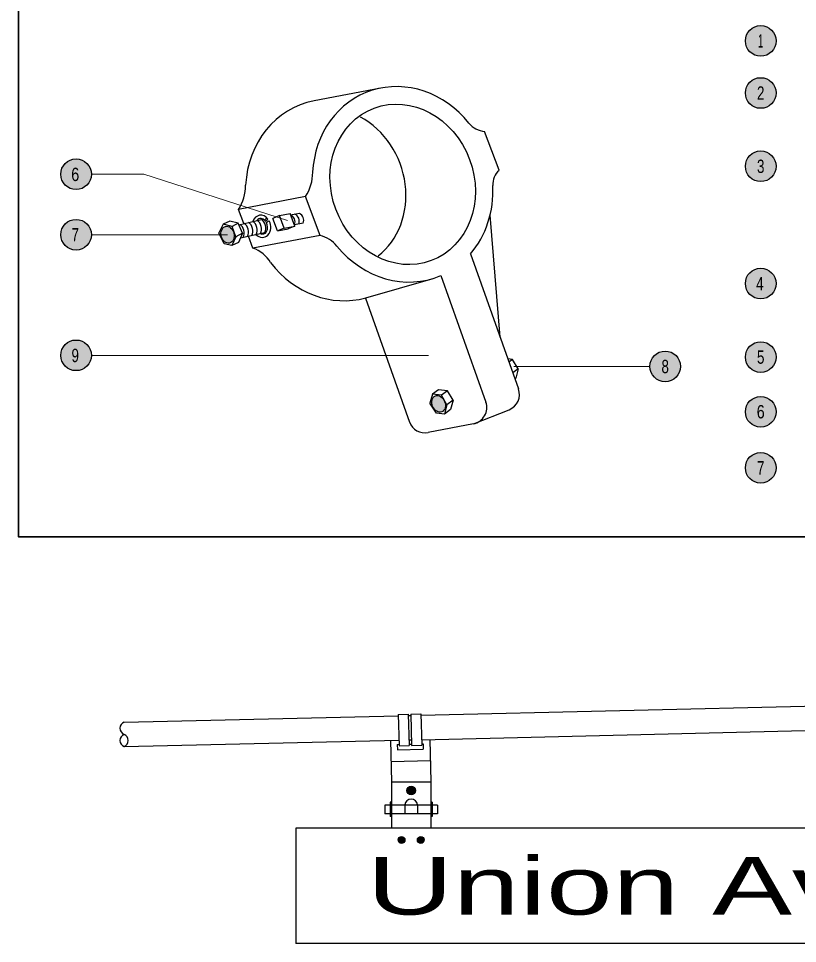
# Model space of a CAD drawing. Extents: x 312583 to 312853, y 144376 to 144586.
# Drawn here: x 312727.3 to 312771.1, y 144475.2 to 144527.1 of the extents above; entities that cross this region are included whole.
import ezdxf
from ezdxf.enums import TextEntityAlignment as Align

# ---------------------------------------------------------------- set-up
doc = ezdxf.new("R2010")
doc.units = 0
doc.header["$LTSCALE"] = 0.3
doc.layers.add('1', color=7, linetype='Continuous', lineweight=25)
doc.layers.add('2', color=7, linetype='Continuous', lineweight=13)

msp = doc.modelspace()

# ---------------------------------------------------------------- hatches: boundary and pattern name
at = {"layer": '1'}
h = msp.add_hatch(color=256, dxfattribs=at)
edge = h.paths.add_edge_path()
edge.add_ellipse((312739.0765, 144514.9847), major_axis=(0.1132, -0.4662), ratio=0.761491, start_angle=0, end_angle=360)
h = msp.add_hatch(color=256, dxfattribs=at)
edge = h.paths.add_edge_path()
edge.add_ellipse((312750.9188, 144505.4948), major_axis=(0.1834, -0.4433), ratio=0.761491, start_angle=0, end_angle=360)
for points in [[(312749.6201, 144483.7997, 1), (312749.1381, 144483.7997, 1)], [(312749.5488, 144483.7997, 1), (312749.2094, 144483.7997, 1)], [(312749.0308, 144481.0248, 1), (312748.6485, 144481.0248, 1)], [(312750.1096, 144481.0248, 1), (312749.7273, 144481.0248, 1)]]:
    msp.add_hatch(color=256, dxfattribs=at).paths.add_polyline_path(points)
at = {"layer": '2'}
for points in [[(312769.8524, 144525.8569, 1), (312768.1321, 144525.8569, 1)], [(312769.8524, 144522.9359, 1), (312768.1321, 144522.9359, 1)], [(312769.8524, 144518.8226, 1), (312768.1321, 144518.8226, 1)], [(312731.4329, 144518.3756, 1), (312729.7127, 144518.3756, 1)], [(312731.4329, 144514.9863, 1), (312729.7127, 144514.9863, 1)], [(312769.8524, 144512.2449, 1), (312768.1321, 144512.2449, 1)], [(312731.4329, 144508.217, 1), (312729.7127, 144508.217, 1)], [(312769.8524, 144508.1186, 1), (312768.1321, 144508.1186, 1)], [(312764.4923, 144507.5966, 1), (312762.772, 144507.5966, 1)], [(312769.8524, 144505.0489, 1), (312768.1321, 144505.0489, 1)], [(312769.8524, 144501.9057, 1), (312768.1321, 144501.9057, 1)]]:
    msp.add_hatch(color=256, dxfattribs=at).paths.add_polyline_path(points)

# ---------------------------------------------------------------- linework, layer by layer
at = {"layer": '1'}
for p, q in [((312747.6675, 144523.2086), (312743.9263, 144522.4955)), ((312754.3164, 144518.5969), (312753.5015, 144520.7731)), ((312743.454, 144517.1245), (312739.6851, 144516.4022)), ((312744.2689, 144514.9484), (312743.454, 144517.1245)), ((312739.9907, 144515.6058), (312739.6851, 144516.4022)), ((312739.7036, 144515.541), (312740.9723, 144515.8374)), ((312741.1482, 144515.8003), (312741.2779, 144515.9392)), ((312741.2038, 144515.754), (312741.3427, 144515.8651)), ((312741.2501, 144515.6707), (312741.4168, 144515.7633)), ((312741.9816, 144516.0596), (312741.6112, 144515.9022)), ((312741.8798, 144515.1984), (312741.6112, 144515.9022)), ((312741.9816, 144516.0596), (312742.5836, 144516.18)), ((312742.2502, 144515.3558), (312741.9816, 144516.0596)), ((312742.8521, 144515.4669), (312742.5836, 144516.18)), ((312742.6113, 144516.0966), (312743.1021, 144516.1892)), ((312754.3719, 144509.2348), (312753.8071, 144516.0874)), ((312738.8239, 144515.5781), (312738.5924, 144515.0965)), ((312739.6666, 144515.6244), (312739.3239, 144515.4392)), ((312739.9073, 144515.0688), (312739.6666, 144515.6244)), ((312742.2502, 144515.3558), (312741.8798, 144515.1984)), ((312741.8798, 144515.1984), (312742.4817, 144515.3095)), ((312742.2502, 144515.3558), (312742.8521, 144515.4669)), ((312742.8521, 144515.4669), (312742.4817, 144515.3095)), ((312742.8243, 144515.5503), (312743.3151, 144515.6429)), ((312739.9073, 144515.0688), (312739.6943, 144514.5502)), ((312739.7962, 144514.8095), (312741.1575, 144515.1058)), ((312740.5, 144514.2261), (312740.2407, 144514.9021)), ((312744.2689, 144514.9484), (312740.5, 144514.2261)), ((312739.6943, 144514.5502), (312739.3147, 144514.3742)), ((312752.7051, 144513.9112), (312755.3998, 144506.3363)), ((312751.0382, 144512.6888), (312753.5663, 144505.5954)), ((312746.8248, 144511.4387), (312750.6123, 144512.5314)), ((312746.8063, 144511.4294), (312749.2788, 144504.4749)), ((312755.0665, 144507.9846), (312754.7979, 144508.0124)), ((312755.0665, 144507.9846), (312754.8627, 144507.8272)), ((312755.3906, 144507.466), (312755.0665, 144507.9846)), ((312755.3906, 144507.466), (312755.0757, 144507.2345)), ((312755.3906, 144507.466), (312755.2517, 144506.9289)), ((312755.2517, 144506.9289), (312755.2054, 144506.8919)), ((312750.566, 144506.0307), (312750.4178, 144505.5306)), ((312751.4086, 144506.2251), (312751.0845, 144505.9751)), ((312751.7328, 144505.7066), (312751.4086, 144506.2251)), ((312751.7328, 144505.7066), (312751.5939, 144505.1695)), ((312752.8718, 144504.3731), (312754.872, 144505.1602)), ((312752.8718, 144504.3731), (312750.3252, 144503.8823)), ((312749.9268, 144488.0237), (312774.5963, 144488.6071)), ((312733.2675, 144487.6348), (312748.6489, 144487.9959)), ((312748.6489, 144488.07), (312749.2138, 144488.0885)), ((312748.6489, 144488.07), (312748.6952, 144486.3105)), ((312749.2138, 144488.0885), (312749.2601, 144486.3291)), ((312749.2138, 144488.0052), (312749.3527, 144488.0144)), ((312749.3527, 144488.0885), (312749.9268, 144488.0978)), ((312749.3527, 144488.0885), (312749.399, 144486.3291)), ((312749.9268, 144488.0978), (312749.9731, 144486.3383)), ((312749.9639, 144486.6532), (312774.6334, 144487.2366)), ((312750.4269, 144486.6624), (312750.4825, 144484.2825)), ((312733.2675, 144486.2642), (312748.686, 144486.6254)), ((312748.2229, 144486.6161), (312748.2785, 144484.2825)), ((312748.5934, 144486.3846), (312748.6952, 144486.3939)), ((312748.5934, 144486.3846), (312748.6026, 144486.079)), ((312748.6952, 144486.3105), (312749.2601, 144486.3291)), ((312749.2508, 144486.6439), (312749.3897, 144486.6439)), ((312749.2601, 144486.3939), (312749.399, 144486.4031)), ((312749.399, 144486.3291), (312749.9731, 144486.3383)), ((312749.9731, 144486.4217), (312750.0472, 144486.4217)), ((312750.0472, 144486.4217), (312750.0565, 144486.1161)), ((312748.6026, 144486.079), (312750.0565, 144486.1161)), ((312748.2507, 144485.4308), (312750.4547, 144485.4864)), ((312748.2785, 144484.2825), (312748.2785, 144481.6896)), ((312748.2785, 144484.2825), (312750.4825, 144484.2825)), ((312750.4825, 144484.2825), (312750.4825, 144481.6896)), ((312748.2044, 144483.1435), (312748.2044, 144482.3471)), ((312748.2785, 144483.1435), (312748.2044, 144483.1435)), ((312750.5565, 144483.1435), (312750.4825, 144483.1435)), ((312750.5565, 144483.1435), (312750.5565, 144482.3471)), ((312747.9081, 144482.9861), (312747.9081, 144482.4953)), ((312748.2044, 144482.9861), (312747.9081, 144482.9861)), ((312748.2044, 144482.4953), (312747.9081, 144482.4953)), ((312750.4825, 144482.9861), (312748.2785, 144482.9861)), ((312750.4825, 144482.4953), (312748.2785, 144482.4953)), ((312749.0286, 144482.9861), (312749.0286, 144482.4953)), ((312749.7324, 144482.9861), (312749.7324, 144482.4953)), ((312750.8529, 144482.9861), (312750.5565, 144482.9861)), ((312750.8529, 144482.4953), (312750.5565, 144482.4953)), ((312750.8529, 144482.9861), (312750.8529, 144482.4953)), ((312748.2785, 144482.3471), (312748.2044, 144482.3471)), ((312750.5565, 144482.3471), (312750.4825, 144482.3471)), ((312781.8194, 144481.6896), (312742.9075, 144481.6896)), ((312742.9075, 144481.6896), (312742.9075, 144475.2167)), ((312781.8194, 144475.2167), (312742.9075, 144475.2167))]:
    msp.add_line(p, q, dxfattribs=at)
at = {"layer": '1', "lineweight": 35}
msp.add_lwpolyline([(312727.3426, 144585.0846), (312727.3426, 144498.0376), (312849, 144498.0376)], dxfattribs=at)
at = {"layer": '1'}
for points in [[(312739.6666, 144515.6244), (312739.1943, 144515.7448), (312738.8239, 144515.5781)], [(312739.5369, 144514.865), (312739.3239, 144515.4392), (312738.8239, 144515.5781)], [(312739.3054, 144514.3835), (312738.8794, 144514.4761), (312738.5924, 144515.0965)], [(312739.9073, 144515.0688), (312739.5369, 144514.865), (312739.3054, 144514.3835)], [(312751.4086, 144506.2251), (312750.9086, 144506.2807), (312750.566, 144506.0307)], [(312751.3809, 144505.4473), (312751.0845, 144505.9751), (312750.566, 144506.0307)], [(312751.5939, 144505.1695), (312751.242, 144504.9194), (312750.8067, 144504.975), (312750.4178, 144505.5306)], [(312751.7328, 144505.7066), (312751.3809, 144505.4473), (312751.242, 144504.9194)]]:
    msp.add_lwpolyline(points, dxfattribs=at)
for centre, radius in [((312749.3791, 144483.7997), 0.241), ((312749.3791, 144483.7997), 0.1697), ((312748.8396, 144481.0248), 0.1911), ((312749.9184, 144481.0248), 0.1911)]:
    msp.add_circle(centre, radius, dxfattribs=at)
for centre, radius, start, end in [((312753.6385, 144522.0897), 1.3237, 219.72169, 264.05852), ((312741.3795, 144518.4702), 2.4727, 327.02897, 0.36084), ((312755.0186, 144517.7967), 1.0646, 131.26832, 182.78624), ((312737.6106, 144517.7479), 2.4727, 327.02897, 0.36084), ((312742.4489, 144515.7186), 0.4114, 335.84567, 66.74904), ((312742.6897, 144515.7557), 0.4114, 335.84567, 66.74904), ((312742.9397, 144515.802), 0.4114, 335.84567, 66.74904), ((312743.8194, 144513.2099), 1.7956, 39.19148, 75.5026), ((312739.9367, 144512.5211), 1.7956, 30.05549, 71.71649), ((312754.5286, 144506.0202), 0.926, 291.80141, 19.98311), ((312752.6962, 144505.2855), 0.926, 280.75797, 19.39781), ((312750.1503, 144504.7917), 0.926, 199.83213, 280.7843), ((312733.4053, 144487.2921), 0.3693, 111.90812, 248.09188), ((312733.4053, 144486.6069), 0.3693, 111.90812, 248.09188), ((312733.1297, 144486.6069), 0.3693, 291.90812, 68.09187), ((312749.379, 144482.9614), 0.3533, 5.25702, 174.74298)]:
    msp.add_arc(centre, radius, start, end, dxfattribs=at)
for centre, major_axis, ratio, start_param, end_param in [((312748.9029, 144517.8108), (1.9393, -5.2001), 0.898961, 1.9230661, 4.2654202), ((312745.1432, 144517.0885), (1.9393, -5.2001), 0.898961, 2.990624, 4.2654501), ((312745.0043, 144517.57), (1.5962, -4.2801), 0.877241, 0.2627211, 2.3551549), ((312748.9029, 144517.8108), (1.9393, -5.2001), 0.898961, 0.4565584, 1.2353233), ((312740.9841, 144515.457), (0.1482, -0.6104), 0.817859, 2.0914245, 4.0693394), ((312740.364, 144515.3096), (0.1132, -0.4662), 0.761491, 0.6824826, 2.4633871), ((312740.9841, 144515.457), (0.1482, -0.6104), 0.817859, 5.342727, 8.1654114), ((312740.9841, 144515.457), (0.1048, -0.4316), 0.742407, 2.128478, 3.7087249), ((312740.6069, 144515.3656), (0.1132, -0.4662), 0.761491, 0.6737973, 2.4658919), ((312740.8485, 144515.4124), (0.1132, -0.4662), 0.761491, 0.6928396, 2.4979168), ((312739.635, 144515.1417), (0.1132, -0.4662), 0.761491, 0.7080194, 2.4492975), ((312739.878, 144515.1976), (0.1132, -0.4662), 0.761491, 0.6995905, 2.458401), ((312740.121, 144515.2536), (0.1132, -0.4662), 0.761491, 0.6910793, 2.4608902), ((312740.9841, 144515.457), (0.1048, -0.4316), 0.742407, 5.721647, 8.1879522), ((312748.9029, 144517.8108), (1.9393, -5.2001), 0.898961, 5.0733082, 6.3254865), ((312745.2728, 144516.7643), (1.9393, -5.2001), 0.898961, 5.0451183, 6.2015639), ((312747.1897, 144517.2922), (1.9393, -5.2001), 0.898961, 0.0420677, 0.0423012)]:
    msp.add_ellipse(centre, major_axis=major_axis, ratio=ratio, start_param=start_param, end_param=end_param, dxfattribs=at)
for centre, major_axis, ratio in [((312748.9029, 144517.8108), (1.5962, -4.2801), 0.877241), ((312739.0765, 144514.9847), (0.1132, -0.4662), 0.761491), ((312750.9188, 144505.4948), (0.1834, -0.4433), 0.761491)]:
    msp.add_ellipse(centre, major_axis=major_axis, ratio=ratio, dxfattribs=at)
at = {"layer": '2'}
for p, q in [((312731.4341, 144514.9854), (312739.0739, 144514.9854)), ((312731.4341, 144508.2161), (312750.353, 144508.2161)), ((312755.1313, 144507.5957), (312762.7711, 144507.5957))]:
    msp.add_line(p, q, dxfattribs=at)
msp.add_lwpolyline([(312731.4341, 144518.3747), (312734.3697, 144518.3747), (312742.4354, 144515.7911)], dxfattribs=at)
at = {"layer": '2', "lineweight": 25}
for centre in [(312768.9923, 144525.8569), (312768.9923, 144522.9359), (312768.9923, 144518.8226), (312730.5728, 144518.3756), (312730.5728, 144514.9863), (312768.9923, 144512.2449), (312730.5728, 144508.217), (312768.9923, 144508.1186), (312763.6321, 144507.5966), (312768.9923, 144505.0489), (312768.9923, 144501.9057)]:
    msp.add_circle(centre, 0.8601, dxfattribs=at)

# ---------------------------------------------------------------- texts
at = {"layer": '1', "width": 1.55}
msp.add_text('Union Ave', height=3.236, dxfattribs=at).set_placement((312762.3588, 144476.8372), align=Align.CENTER)
at = {"layer": '2'}
for s, height, width, p in [('1', 0.7505, 0.5, (312768.9877, 144525.4862)), ('2', 0.7505, 0.75, (312768.9924, 144522.56)), ('3', 0.7505, 0.75, (312768.9924, 144518.4484)), ('6', 0.7501, 0.8, (312730.5266, 144517.995)), ('7', 0.7501, 0.75, (312730.5266, 144514.6057)), ('4', 0.7505, 0.75, (312768.9461, 144511.8643)), ('9', 0.7501, 0.75, (312730.5266, 144507.8364)), ('5', 0.7505, 0.75, (312768.9924, 144507.7434)), ('8', 0.7501, 0.75, (312763.6323, 144507.216)), ('6', 0.7501, 0.8, (312768.9924, 144504.6783)), ('7', 0.7501, 0.75, (312768.9924, 144501.5298))]:
    msp.add_text(s, height=height, dxfattribs=dict(at, width=width)).set_placement(p, align=Align.CENTER)

doc.saveas('drawing.dxf')
